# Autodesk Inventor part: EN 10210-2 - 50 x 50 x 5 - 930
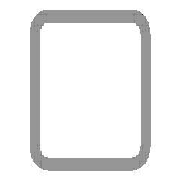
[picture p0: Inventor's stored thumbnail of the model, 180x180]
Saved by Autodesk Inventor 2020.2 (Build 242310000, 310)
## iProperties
IsCustomPart: 1
_CCFamilyMember: 16
_CCFamilyDisplayName: DIN EN 10210-2 (USAS B17.1 quadratisch) - Rohrleitung — In Klammern angegebene Größen wurden aufgehoben
_FrameMemberDoc: Frame Member File
_Version: 15.0.0
_GetPNFromCC: 1
Created: 2019-10
Part Number: EN 10210-2 - 50 x 50 x 5 - 930
Material: Stahl, weich
Description: Rohrleitung
Document SubType Name: Modeling
Standard: DIN
Designer: lutzd
Standard Revision: 2006-07
Standards Organization: DIN
Language: de-DE
Size Designation: 50 x 50 x 5
Categories: <MemberInstance><Categories><Category DisplayName="Profile" InternalName="089c4875-fa83-4c05-b084-43b9cc11f5ed" Mnemonic="GRDR"><CategoryParameter DisplayName="
Stock Number: 50 x 50 x 5
Mass: 6374.61 g
Surface Area: 3165.88 cm^2
Volume: 812.053 cm^3
Density: 7.85 g/cm^3
Appearance: Semi-Polished(8)
G_L: 930,000 mm
G_W: 50,000 mm
G_H: 50,000 mm
Dimensions: 50x50x930 mm
Mass: 6,375 kg
DocNumber: ADSK-014299
Folder: .
+01D472B3-B18E-4D65-BD7D-2CA1511B1DC5+SCHNITTDETAIL1: Schnittwinkel 90,00 grd
+28310AD1-AEBE-4B39-B138-04B7BFB78A9F+SCHNITTDETAIL2: Schnittwinkel 90,00 grd
VLT_Material: Stahl, weich
Title: Profil-Bauteil
Author: lutzd
Revision Number: -
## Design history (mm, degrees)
node "Startebene"
node "Endebene"
sketch "Skizze"
  geometry: L1 (-25, -17.5)-(-25, 17.5); L2 (-17.5, 25)-(17.5, 25); L3 (25, 17.5)-(25, -17.5); L4 (17.5, -25)-(-17.5, -25); L5 (-15, 20)-(15, 20); L6 (20, 15)-(20, -15); L7 (15, -20)-(-15, -20); L8 (-20, -15)-(-20, 15); L9 (0, 37.175)-(0, -37.175) reference; L10 (-37.175, 0)-(37.175, 0) reference; A1 r 7.5 centre (-17.5, -17.5) between (-25, -17.5) and (-17.5, -25); A2 r 7.5 centre (-17.5, 17.5) between (-17.5, 25) and (-25, 17.5); A3 r 7.5 centre (17.5, 17.5) between (25, 17.5) and (17.5, 25); A4 r 7.5 centre (17.5, -17.5) between (17.5, -25) and (25, -17.5); A5 r 5 centre (-15, -15) between (-20, -15) and (-15, -20); A6 r 5 centre (-15, 15) between (-15, 20) and (-20, 15); A7 r 5 centre (15, 15) between (20, 15) and (15, 20); A8 r 5 centre (15, -15) between (15, -20) and (20, -15)
  constraints: 16 end point, 16 point on circle, 16 tangent, 8 centre point, 6 equal radius, 4 parallel, 2 perpendicular, 2 other
  dimensions: "d7" = 7.5 radius of A1 (= G_IR); "d10" = 50 distance between parallel lines of L2 L4 (= G_H); "d11" = 50 distance between parallel lines of L1 L3 (= G_W); "d12" = 5 distance between parallel lines of L3 L6 (= G_T); "d15" = 25 distance between parallel lines of L2 L10 (= 0.5 x d10); "d16" = 25 distance between parallel lines of L9 L3 (= 0.5 x d11); "d19" = 5 radius of A5 (= G_T); "d20" = 5 distance between parallel lines of L4 L7 (= G_T)
extrude "Körper" new body sketch "Skizze" stored distance "d3" = 930 (= G_L); taper "d4" = 0 deg
node "Driven Length"
  sketch "Sketch3"
    geometry: L1 (0, 0)-(10, 0) reference
    constraints: 2 end point, 1 horizontal
  workplane "Work Plane3"
  sketch "Sketch4"
    geometry: L1 (-2, 50)-(12, 50) reference; L2 (-2, 980)-(12, 980) reference
    dimensions: "d18" = 930 distance between parallel lines of L1 L2 (derived)
workplane "Arbeitsebene4"
feature "Trennen1"
workplane "Arbeitsebene5"
feature "Trennen2"
body "Solid1"
other parameters: "G_W" = 50 [user parameter; used in 1 equation term], "G_H" = 50 [user parameter; used in 1 equation term], "G_T" = 5 [user parameter; used in 3 equation terms], "G_IR" = 7.5 [user parameter; used in 1 equation term], "G_L" = 930 (= d18) [user parameter; used in 1 equation term], "d17" = 90 deg
